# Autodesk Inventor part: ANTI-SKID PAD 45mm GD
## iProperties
Created: 2007-03
Part Number: ANTI-SKID PAD 45mm GD
Document SubType Name: Modeling
Designer: Andy Moles
Material: Rubber
Mass: 7.81813 g
Surface Area: 37.8743 cm^2
Volume: 8.40659 cm^3
Density: 0.93 g/cm^3
Author: Andy Moles
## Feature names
1. Revolution1
